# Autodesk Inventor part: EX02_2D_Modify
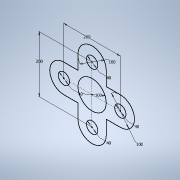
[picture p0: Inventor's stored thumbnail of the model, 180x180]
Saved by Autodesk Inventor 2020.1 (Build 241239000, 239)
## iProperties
Created: 2019-10
Part Number: EX02_2D_Modify
Material: Generic
Document SubType Name: Modeling
Designer: Synergysoft Dell02
Density: 1 g/cm^3
Appearance: Default
Author: Synergysoft Dell02
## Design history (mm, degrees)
sketch "Sketch1"
  geometry: L1 (-100, 0)-(100, 0); L2 (0, -100)-(0, 100); L3 (-50, 100)-(-50, 50); L4 (100, 50)-(50, 50); L5 (-50, 50)-(-100, 50); L6 (50, -100)-(50, -50); L7 (50, 50)-(50, 100); L8 (-50, -50)-(-50, -100); L9 (-100, -50)-(-50, -50); L10 (50, -50)-(100, -50); C1 r 50 at (0, 0); C2 r 20 at (0, 100); C3 r 20 at (100, 0); C4 r 20 at (0, -100); C5 r 20 at (-100, 0); A1 r 50 centre (-100, 0) between (-100, 50) and (-100, -50); A2 r 50 centre (100, 0) between (100, -50) and (100, 50); A3 r 50 centre (0, -100) between (-50, -100) and (50, -100); A4 r 50 centre (0, 100) between (50, 100) and (-50, 100); 3 further points
  constraints: 24 end point, 16 tangent, 9 centre point, 8 parallel, 8 point on circle, 4 coincident, 3 concentric, 2 midpoint, 1 horizontal, 1 vertical
  dimensions: "d2" = 200 distance of L1.start L1.end; "d3" = 100 diameter of A2; "d14" = 200 distance of L2.start L2.end; "d15" = 100 diameter of A4; "d16" = 100 diameter of C1; "d17" = 40 diameter of C2; "d18" = 40 diameter of C3; "d19" = 40 diameter of C4; "d20" = 40 diameter of C5
